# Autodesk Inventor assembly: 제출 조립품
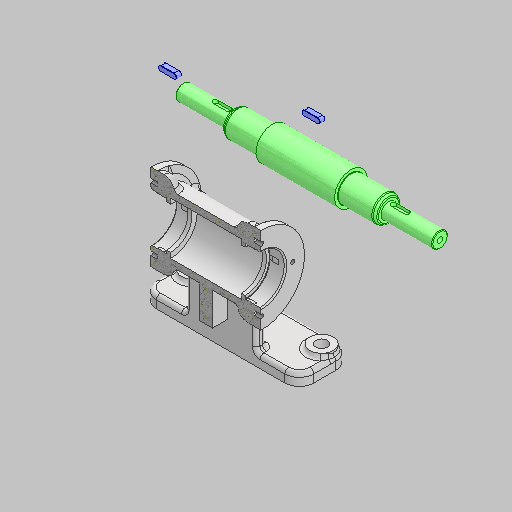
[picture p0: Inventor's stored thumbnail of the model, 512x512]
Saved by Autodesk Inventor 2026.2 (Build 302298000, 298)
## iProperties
Created: 2026-06
Part Number: 제출 조립품
Document SubType Name: Assembly
Designer: sec7
Author: sec7
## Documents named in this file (4)
- C:\Users\sec7\Desktop\최진선\제출 조립품.iam
- C:\Users\sec7\Desktop\최진선\본체.ipt
- C:\Users\sec7\Desktop\최진선\축.ipt
- C:\Users\sec7\Desktop\최진선\평행 키 4x4x14.ipt
